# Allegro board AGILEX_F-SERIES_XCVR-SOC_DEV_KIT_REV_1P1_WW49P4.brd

Outline 218.44 x 218.44 mm; copper layers: TOP, GND02, ART03, GND04, ART05, GND06, ART07, GND08, POWER09, GND10, POWER11, POWER12, GND13, POWER14, GND15, ART16, GND17, ART18, GND19, ART20, GND21, BOTTOM. Coordinates in mm from the lower left corner of the outline.
Outline path: 0,217.17 arc(0.37,218.07) 1.27,218.44 217.17,218.44 arc(218.07,218.07) 218.44,217.17 218.44,1.27 arc(218.07,0.37) 217.17,0 1.27,0 arc(0.37,0.37) 0,1.27 0,217.17

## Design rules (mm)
constraint set DEFAULT: min track width 0.109
net group AGND_1.8V: nets EN_1.8V N25097889
net group AGND_2.5V: nets EN_2.5V N25103528
net group AGND_VCCIO_FPGA_1.2V: nets EN_VCCIO_FPGA_1.2V N25225151
net group AGND_VCCIO_FPGA_1.5V: nets EN_VCCIO_FPGA_1.5V N25087496
net group AGND_VCCIO_FPGA_1.8V: nets EN_VCCIO_FPGA_1.8V N25083983
net group AGND_VCCL_HPS_FPGA_0.9V: nets EN_VCCL_HPS_FPGA_0.9V N25074810
net group AGND_VCCL_SDM_FPGA_0.8V: nets EN_VCCL_SDM_FPGA_0.8V N25076947
net group AVST_CLK: nets AVST_CLK N18693741
net group CLEANER_IN0_N: nets CLEANER_IN0_N CLEARNER_RECOVERY_N0
net group CLEANER_IN0_P: nets CLEANER_IN0_P CLEARNER_RECOVERY_P0
net group CLEANER_IN1_N: nets CLEANER_IN1_N CLEARNER_RECOVERY_N1
net group CLEANER_IN1_P: nets CLEANER_IN1_P CLEARNER_RECOVERY_P1
net group CLEANER_IN2_N: nets CLEANER_IN2_N CLEARNER_RECOVERY_N2
net group CLEANER_IN2_P: nets CLEANER_IN2_P CLEARNER_RECOVERY_P2
net group CLK_50M_PWRMAX: nets CLK_50M_PWRMAX N17552752
net group CLK_50M_SYSMAX: nets CLK_50M_SYSMAX N18161617
net group CLS_40OHM: nets DDR4_COMP_ALERTN DDR4_COMP_RESETN
net group CLS_EXT_JTAG: nets JTAG_RX JTAG_TX
net group CLS_FX2: nets FX2_RESETN FX2_WAKEUP
net group CLS_FX2_USB: nets FX2_DN FX2_DP
net group CLS_GND_E: nets GND_ETHE GND_QSFP_CAGE
net group CLS_MEMORY_DDR4_CAC: nets DDR4_COMP_RZQ DDR4_COMP_TEN
net group CLS_SODIMM_CLK: nets MEM_CLKN MEM_CLKP
net group CLS_SODIMM_D8: nets MEM_DQ_ADDR_CMD4 MEM_DQ_ADDR_CMD7
net group DIFFPAIR19: nets N17498635 N17498650
net group DIFFPAIR20: nets N17498657 N17498668
net group DIFFPAIR21: nets N17498677 N17498690
net group DIFFPAIR22: nets N17498697 N17498704
net group DIFFPAIR23: nets N18253290 N18253428
net group DIFFPAIR24: nets N18253296 N18253441
net group DIFFPAIR25: nets N18253303 N18253449
net group DIFFPAIR26: nets N18253309 N18253452
net group EN0_1.8V_R: nets EN0_1.8V_R EN_VCCPT_FPGA_1.8V
net group EN0_3.3V_R: nets EN0_3.3V_R EN_3.3V
net group EN_1.2V: nets EN_1.2V N25917150
net group EN_VCCCLK_GXE_FPGA_2.5V: nets EN_VCCCLK_GXE_FPGA_2.5V N25909453
net group EN_VCCFUSEWR_SDM_FPGA_2.4V: nets EN_VCCFUSEWR_SDM_FPGA_2.4V N25913473
net group EN_VCCH_GXE_FPGA_1.1V: nets EN_VCCH_GXE_FPGA_1.1V N25080456
net group EN_VTT_DDR4_0.6V: nets EN_VTT_DDR4_0.6V N24985018
net group EN_VTT_SODIMM_0.6V: nets EN_VTT_SODIMM_0.6V N24984146
net group ETH_T_SGMII_TXN: nets ETH_SGMII_TXN ETH_T_SGMII_TXN
net group ETH_T_SGMII_TXP: nets ETH_SGMII_TXP ETH_T_SGMII_TXP
net group FAN_RPM: nets FAN_RPM N18990186
net group FLASH_DC0_IO0: nets FLASH_DC0_IO0 SDM_IO2
net group FLASH_DC0_IO2: nets FLASH_DC0_IO2 SDM_IO5
net group FLASH_DC0_IO3: nets FLASH_DC0_IO3 SDM_IO1
net group FLASH_DC0_IO5: nets FLASH_DC0_IO5 SDM_IO6
net group FLASH_DC0_IO6: nets FLASH_DC0_IO6 SDM_IO9
net group FLASH_DC0_IO7: nets FLASH_DC0_IO7 SDM_IO7
net group FLASH_DC0_IO9: nets FLASH_DC0_IO9 SDM_IO13
net group FLASH_DC0_IO12: nets SDM_IO11 SDM_IO16
net group FPGA_GPIO_OUTCLKN: nets FPGA_GPIO_OUTCLKN N18623017
net group FPGA_GPIO_OUTCLKP: nets FPGA_GPIO_OUTCLKP N18624759
net group FPGA_GPIO_REFCLK: nets FPGA_GPIO_REFCLK SI5338_1_CLK2P
net group FPGA_GPIO_REFCLKN2: nets FPGA_GPIO_REFCLKN2 N18624288
net group FPGA_GPIO_REFCLKP2: nets FPGA_GPIO_REFCLKP2 N18624358
net group FPGA_SYSTEM_CLK: nets FPGA_SYSTEM_CLK SI5338_1_CLK0P
net group FPGA_TEMP0: nets FPGA_TEMP0N FPGA_TEMP0P
net group FPGA_TEMP1: nets FPGA_TEMP1N FPGA_TEMP1P
net group FPGA_TEMP2: nets FPGA_TEMP2N FPGA_TEMP2P
net group FPGA_TEMP3: nets FPGA_TEMP3N FPGA_TEMP3P
net group FX2_SCL: nets FX2_SCL PHY_SCL
net group FX2_SDA: nets FX2_SDA PHY_SDA
net group GNDSENSE: nets GNDSENSE VCCLSENSE
net group HPS_GPIO28: nets HPS_GPIO28 HPS_GPIO28_R
net group HPS_GPIO29: nets HPS_GPIO29 HPS_GPIO29_R
net group I2C_3.3V_SDA: nets I2C_3.3V_SCL I2C_3.3V_SDA
net group I2C_PCIE_SCL: nets I2C_PCIE_SCL N20316912
net group I2C_PCIE_SDA: nets I2C_PCIE_SDA N20316908
net group I2C_VID_SDA: nets I2C_VID_SCL I2C_VID_SDA
net group ISENSE_12VIN: nets ISENSE_12VIN N18163063
net group ISENSEN_VCCIO_FPGA_1.8V: nets ISENSEN_VCCIO_FPGA_1.8V ISENSEP_VCCIO_FPGA_1.8V
net group ISENSEP_VCCCLK_GXE_FPGA_2.5V: nets ISENSEN_VCCCLK_GXE_FPGA_2.5V ISENSEP_VCCCLK_GXE_FPGA_2.5V
net group ISENSEP_VCCFUSEWR_SDM_FPGA_2.4V: nets ISENSEN_VCCFUSEWR_SDM_FPGA_2.4V ISENSEP_VCCFUSEWR_SDM_FPGA_2.4V
net group ISENSEP_VCCH_GXE_FPGA_1.1V: nets ISENSEN_VCCH_GXE_FPGA_1.1V ISENSEP_VCCH_GXE_FPGA_1.1V
net group ISENSEP_VCCIO_FPGA_1.5V: nets ISENSEN_VCCIO_FPGA_1.5V ISENSEP_VCCIO_FPGA_1.5V
net group ISENSEP_VCCL_HPS_FPGA_0.9V: nets ISENSEN_VCCL_HPS_FPGA_0.9V ISENSEP_VCCL_HPS_FPGA_0.9V
net group ISENSEP_VCCL_SDM_FPGA_0.8V: nets ISENSEN_VCCL_SDM_FPGA_0.8V ISENSEP_VCCL_SDM_FPGA_0.8V
net group ISENSEP_VDD_SODIMM: nets ISENSEN_VDD_SODIMM ISENSEP_VDD_SODIMM
net group MG_AVST_U29-U1: nets AVST_D24 AVST_READY
net group MXP_RXP0: nets MXP_RXN0 MXP_RXP0
net group MXP_RXP1: nets MXP_RXN1 MXP_RXP1
net group MXP_RXP2: nets MXP_RXN2 MXP_RXP2
net group MXP_RXP3: nets MXP_RXN3 MXP_RXP3
net group MXP_TXP0: nets MXP_TXN0 MXP_TXP0
net group MXP_TXP1: nets MXP_TXN1 MXP_TXP1
net group MXP_TXP2: nets MXP_TXN2 MXP_TXP2
net group MXP_TXP3: nets MXP_TXN3 MXP_TXP3
net group N18609511: nets N18609511 N19994522
net group N19994036: nets N19994036 N21454939
net group N20035742: nets N20035658 N20035742
net group OPT_FAN_RPM: nets N18990913 OPT_FAN_RPM
net group PCIE_RC_REFCLKN: nets N20604746 PCIE_RC_REFCLKN
net group PCIE_RC_REFCLKP: nets N20604729 PCIE_RC_REFCLKP
net group PCIE_RC_RXP0: nets PCIE_RC_RXN0 PCIE_RC_RXP0
net group PCIE_RC_RXP1: nets PCIE_RC_RXN1 PCIE_RC_RXP1
net group PCIE_RC_RXP2: nets PCIE_RC_RXN2 PCIE_RC_RXP2
net group PCIE_RC_RXP3: nets PCIE_RC_RXN3 PCIE_RC_RXP3
net group PCIE_RC_RXP4: nets PCIE_RC_RXN4 PCIE_RC_RXP4
net group PCIE_RC_RXP5: nets PCIE_RC_RXN5 PCIE_RC_RXP5
net group PCIE_RC_RXP6: nets PCIE_RC_RXN6 PCIE_RC_RXP6
net group PCIE_RC_RXP7: nets PCIE_RC_RXN7 PCIE_RC_RXP7
net group PCIE_RC_RXP8: nets PCIE_RC_RXN8 PCIE_RC_RXP8
net group PCIE_RC_RXP9: nets PCIE_RC_RXN9 PCIE_RC_RXP9
net group PCIE_RC_RXP10: nets PCIE_RC_RXN10 PCIE_RC_RXP10
net group PCIE_RC_RXP11: nets PCIE_RC_RXN11 PCIE_RC_RXP11
net group PCIE_RC_RXP12: nets PCIE_RC_RXN12 PCIE_RC_RXP12
net group PCIE_RC_RXP13: nets PCIE_RC_RXN13 PCIE_RC_RXP13
net group PCIE_RC_RXP14: nets PCIE_RC_RXN14 PCIE_RC_RXP14
net group PCIE_RC_RXP15: nets PCIE_RC_RXN15 PCIE_RC_RXP15
net group PCIE_RC_TXP0: nets PCIE_RC_TXN0 PCIE_RC_TXP0
net group PCIE_RC_TXP1: nets PCIE_RC_TXN1 PCIE_RC_TXP1
net group PCIE_RC_TXP2: nets PCIE_RC_TXN2 PCIE_RC_TXP2
net group PCIE_RC_TXP3: nets PCIE_RC_TXN3 PCIE_RC_TXP3
net group PCIE_RC_TXP4: nets PCIE_RC_TXN4 PCIE_RC_TXP4
net group PCIE_RC_TXP5: nets PCIE_RC_TXN5 PCIE_RC_TXP5
net group PCIE_RC_TXP6: nets PCIE_RC_TXN6 PCIE_RC_TXP6
net group PCIE_RC_TXP7: nets PCIE_RC_TXN7 PCIE_RC_TXP7
net group PCIE_RC_TXP8: nets PCIE_RC_TXN8 PCIE_RC_TXP8
net group PCIE_RC_TXP9: nets PCIE_RC_TXN9 PCIE_RC_TXP9
net group PCIE_RC_TXP10: nets PCIE_RC_TXN10 PCIE_RC_TXP10
net group PCIE_RC_TXP11: nets PCIE_RC_TXN11 PCIE_RC_TXP11
net group PCIE_RC_TXP12: nets PCIE_RC_TXN12 PCIE_RC_TXP12
net group PCIE_RC_TXP13: nets PCIE_RC_TXN13 PCIE_RC_TXP13
net group PCIE_RC_TXP14: nets PCIE_RC_TXN14 PCIE_RC_TXP14
net group PCIE_RC_TXP15: nets PCIE_RC_TXN15 PCIE_RC_TXP15
net group PCIE_TXN0: nets PCIE_TXN0 PCIE_TXP0
net group PCIE_TXN3: nets PCIE_TXN3 PCIE_TXP3
net group PCIE_TXP1: nets PCIE_TXN1 PCIE_TXP1
net group PCIE_TXP2: nets PCIE_TXN2 PCIE_TXP2
net group PCIE_TXP4: nets PCIE_TXN4 PCIE_TXP4
net group PCIE_TXP5: nets PCIE_TXN5 PCIE_TXP5
net group PCIE_TXP6: nets PCIE_TXN6 PCIE_TXP6
net group PCIE_TXP7: nets PCIE_TXN7 PCIE_TXP7
net group PCIE_TXP8: nets PCIE_TXN8 PCIE_TXP8
net group PCIE_TXP9: nets PCIE_TXN9 PCIE_TXP9
net group PCIE_TXP10: nets PCIE_TXN10 PCIE_TXP10
net group PCIE_TXP11: nets PCIE_TXN11 PCIE_TXP11
net group PCIE_TXP12: nets PCIE_TXN12 PCIE_TXP12
net group PCIE_TXP13: nets PCIE_TXN13 PCIE_TXP13
net group PCIE_TXP14: nets PCIE_TXN14 PCIE_TXP14
net group PCIE_TXP15: nets PCIE_TXN15 PCIE_TXP15
net group PWRMAX_DEBUGMDN: nets N20307193 PWRMAX_DEBUGMDN
net group QSFPDD_RXP0: nets QSFPDD_RXN0 QSFPDD_RXP0
net group QSFPDD_RXP1: nets QSFPDD_RXN1 QSFPDD_RXP1
net group QSFPDD_RXP2: nets QSFPDD_RXN2 QSFPDD_RXP2
net group QSFPDD_RXP3: nets QSFPDD_RXN3 QSFPDD_RXP3
net group QSFPDD_RXP4: nets QSFPDD_RXN4 QSFPDD_RXP4
net group QSFPDD_RXP5: nets QSFPDD_RXN5 QSFPDD_RXP5
net group QSFPDD_RXP6: nets QSFPDD_RXN6 QSFPDD_RXP6
net group QSFPDD_RXP7: nets QSFPDD_RXN7 QSFPDD_RXP7
net group QSFPDD_TEMP4P: nets QSFPDD_TEMP4N QSFPDD_TEMP4P
net group QSFPDD_TXP0: nets QSFPDD_TXN0 QSFPDD_TXP0
net group QSFPDD_TXP1: nets QSFPDD_TXN1 QSFPDD_TXP1
net group QSFPDD_TXP2: nets QSFPDD_TXN2 QSFPDD_TXP2
net group QSFPDD_TXP3: nets QSFPDD_TXN3 QSFPDD_TXP3
net group QSFPDD_TXP4: nets QSFPDD_TXN4 QSFPDD_TXP4
net group QSFPDD_TXP5: nets QSFPDD_TXN5 QSFPDD_TXP5
net group QSFPDD_TXP6: nets QSFPDD_TXN6 QSFPDD_TXP6
net group QSFPDD_TXP7: nets QSFPDD_TXN7 QSFPDD_TXP7
net group REFCLK_GXEN1: nets N18946522 REFCLK_GXEN1
net group REFCLK_GXEP1: nets N18946492 REFCLK_GXEP1
net group REFCLK_GXPN0: nets N20604632 REFCLK_GXPN0
net group REFCLK_GXPN2: nets N20604666 REFCLK_GXPN2
net group REFCLK_GXPP0: nets N20604615 REFCLK_GXPP0
net group REFCLK_GXPP2: nets N20604649 REFCLK_GXPP2
net group REFERENCECLK_2: nets CLEARNER_7_1HZ REFERENCECLK_2
net group REFERENCECLK_3: nets CLEARNER_0_1HZ REFERENCECLK_3
net group SMA_REFCLKN: nets N17579380 SMA_REFCLKN
net group SMA_REFCLKP: nets N17579378 SMA_REFCLKP
net group SODIMM_CMD4-5: nets MEM_ADDR_CMD4 MEM_ADDR_CMD5
net group SODIMM_VDDQ_AGND: nets EN_VDD_SODIMM N25093122
net group VCCBAT: nets VCCBAT VCCBAT_FPGA_1.8V
net group VSENSEP_VCC/VSENSEN_VCC: nets VSENSEN_VCC VSENSEP_VCC
net group VSENSEP_VCCH: nets VSENSEN_VCCH VSENSEP_VCCH
net group ZQSFP_RXP0: nets ZQSFP_RXN0 ZQSFP_RXP0
net group ZQSFP_RXP1: nets ZQSFP_RXN1 ZQSFP_RXP1
net group ZQSFP_RXP2: nets ZQSFP_RXN2 ZQSFP_RXP2
net group ZQSFP_RXP3: nets ZQSFP_RXN3 ZQSFP_RXP3
net group ZQSFP_TXP0: nets ZQSFP_TXN0 ZQSFP_TXP0
net group ZQSFP_TXP1: nets ZQSFP_TXN1 ZQSFP_TXP1
net group ZQSFP_TXP2: nets ZQSFP_TXN2 ZQSFP_TXP2
net group ZQSFP_TXP3: nets ZQSFP_TXN3 ZQSFP_TXP3
net group CLEARNER_SYSTEM_N: nets CLEARNER_SYSTEM_N N20550319 N20550321
net group CLEARNER_SYSTEM_P: nets CLEARNER_SYSTEM_P N20550259 N20550288
net group CLK_SE: nets FPGA_OSC_CLK_1
net group CLS_45OHM: nets MEM_ADDR_CMD0 MEM_ADDR_CMD1 MEM_ADDR_CMD2 MEM_ADDR_CMD3 MEM_ADDR_CMD8 MEM_ADDR_CMD9 MEM_ADDR_CMD10 MEM_ADDR_CMD11 MEM_ADDR_CMD12 MEM_ADDR_CMD13 MEM_ADDR_CMD14 MEM_ADDR_CMD15 MEM_ADDR_CMD16 MEM_ADDR_CMD17 MEM_ADDR_CMD18 MEM_ADDR_CMD19 MEM_ADDR_CMD20 MEM_ADDR_CMD21 MEM_ADDR_CMD22 MEM_ADDR_CMD23 MEM_ADDR_CMD24 MEM_ADDR_CMD25 MEM_ADDR_CMD26 MEM_ADDR_CMD28 MEM_ADDR_CMD29 MEM_ADDR_CMD30
net group CLS_CLEANER: nets CLEANER_HW_CTRL CLEANER_STATUS0 CLEANER_STATUS1
net group CLS_CLK_DIFF: nets SI5338_0_CLK0P
net group CLS_CLKCLEANER: nets CLKCLEANER_IO_TSN CLKCLEANER_STATUS0 CLKCLEANER_STATUS1
net group CLS_FLASH_DC0: nets FLASH_DC0_PRSNTN
net group CLS_FLASH_DC1_IO: nets FLASH_DC1_PRSNTN
net group CLS_FPGA_DNU: nets FPGA_DNU_CORE0 FPGA_DNU_CORE1 FPGA_DNU_CORE2 FPGA_DNU_CORNER0 FPGA_DNU_CORNER1 FPGA_DNU_CORNER2 FPGA_DNU_CORNER3 FPGA_DNU_CORNER4 FPGA_DNU_CORNER5 FPGA_DNU_CORNER6 FPGA_DNU_CORNER7 FPGA_DNU_SDM0 FPGA_DNU_SDM1
net group CLS_FPGA_GPIO: nets FPGA_GPIO0 FPGA_GPIO1 FPGA_GPIO2 FPGA_GPIO3 FPGA_GPIO4 FPGA_GPIO5 FPGA_GPIO6 FPGA_GPIO7 FPGA_GPIO8 FPGA_GPIO9 FPGA_GPIO10 FPGA_GPIO11 FPGA_GPIO12 FPGA_GPIO13 FPGA_GPIO14 FPGA_GPIO15
net group CLS_FPGA_PB: nets FPGA_PB0 FPGA_PB1 FPGA_PB2 FPGA_PB3 FPGA_PB4 FPGA_PB5 FPGA_PB6 FPGA_PB7 FPGA_SW0 FPGA_SW1 FPGA_SW2 FPGA_SW3 FPGA_SW4 FPGA_SW5 FPGA_SW6 FPGA_SW7
net group CLS_HPS: nets HPS_DC_PRSNTN HPS_DC_RESETN HPS_PWREN HPS_PWRGD
net group CLS_I2C: nets CLEANER_SCL CLEANER_SDA CLKCLEANER_SCL CLKCLEANER_SDA F2M_I2C_SCL F2M_I2C_SDA FPGA_TEST_SCL FPGA_TEST_SDA FPGA_TESTI2C_SCL FPGA_TESTI2C_SDA M2F_I2C_SCL M2F_I2C_SDA MAX_SCL MAX_SDA QSFP_I2C_SCL QSFP_I2C_SDA QSFPDD_I2C_SCL QSFPDD_I2C_SDA QSFPDD_T_SCL QSFPDD_T_SDA SDM_I2C_SCL SDM_I2C_SDA SODIMM_I2C_SCL SODIMM_I2C_SDA SODIMM_SCL SODIMM_SDA ZQSFP_T_SCL ZQSFP_T_SDA
net group CLS_ISENSEN: nets VSENSE_3.3V_PRE VSENSE_5V VSENSE_12VIN
net group CLS_LED: nets ETH_LED_LINK10 ETH_LED_LINK100 ETH_LED_LINK1000 ETH_LED_RX ETH_LED_TX FPGA_LED_G0 FPGA_LED_G1 FPGA_LED_G2 FPGA_LED_G3 FPGA_LED_G4 FPGA_LED_G5 FPGA_LED_G6 FPGA_LED_G7 PWRMAX_LED_G0 PWRMAX_LED_G1 PWRMAX_LED_R0 PWRMAX_LED_R1 SYSMAX_LED_G0 SYSMAX_LED_G1 SYSMAX_LED_G2 SYSMAX_LED_G3 SYSMAX_LED_G4 SYSMAX_LED_Y0 SYSMAX_LED_Y1
net group CLS_MEMORY_DDR4_0: nets DDR4_COMP_DBIN0 DDR4_COMP_DQ0 DDR4_COMP_DQ2 DDR4_COMP_DQ4 DDR4_COMP_DQ6
net group CLS_MEMORY_DDR4_1: nets DDR4_COMP_DBIN1 DDR4_COMP_DQ8 DDR4_COMP_DQ9 DDR4_COMP_DQ10 DDR4_COMP_DQ11 DDR4_COMP_DQ12 DDR4_COMP_DQ13 DDR4_COMP_DQ14 DDR4_COMP_DQ15
net group CLS_MEMORY_DDR4_2: nets DDR4_COMP_DBIN2 DDR4_COMP_DQ16 DDR4_COMP_DQ17 DDR4_COMP_DQ18 DDR4_COMP_DQ19 DDR4_COMP_DQ20 DDR4_COMP_DQ21 DDR4_COMP_DQ22 DDR4_COMP_DQ23
net group CLS_MEMORY_DDR4_3: nets DDR4_COMP_DBIN3 DDR4_COMP_DQ24 DDR4_COMP_DQ25 DDR4_COMP_DQ26 DDR4_COMP_DQ27 DDR4_COMP_DQ28 DDR4_COMP_DQ29 DDR4_COMP_DQ30 DDR4_COMP_DQ31
net group CLS_MEMORY_DDR4_4: nets DDR4_COMP_DBIN4 DDR4_COMP_DQ32 DDR4_COMP_DQ33 DDR4_COMP_DQ34 DDR4_COMP_DQ35 DDR4_COMP_DQ36 DDR4_COMP_DQ37 DDR4_COMP_DQ38 DDR4_COMP_DQ39
net group CLS_MEMORY_DDR4_5: nets DDR4_COMP_DBIN5 DDR4_COMP_DQ40 DDR4_COMP_DQ41 DDR4_COMP_DQ42 DDR4_COMP_DQ43 DDR4_COMP_DQ44 DDR4_COMP_DQ45 DDR4_COMP_DQ46 DDR4_COMP_DQ47
net group CLS_MEMORY_DDR4_6: nets DDR4_COMP_DBIN6 DDR4_COMP_DQ48 DDR4_COMP_DQ49 DDR4_COMP_DQ50 DDR4_COMP_DQ51 DDR4_COMP_DQ52 DDR4_COMP_DQ53 DDR4_COMP_DQ54 DDR4_COMP_DQ55
net group CLS_MEMORY_DDR4_7: nets DDR4_COMP_DBIN7 DDR4_COMP_DQ56 DDR4_COMP_DQ57 DDR4_COMP_DQ58 DDR4_COMP_DQ59 DDR4_COMP_DQ60 DDR4_COMP_DQ61 DDR4_COMP_DQ62 DDR4_COMP_DQ63
net group CLS_MEMORY_DDR4_8: nets DDR4_COMP_DBIN8 DDR4_COMP_DQ64 DDR4_COMP_DQ65 DDR4_COMP_DQ66 DDR4_COMP_DQ68 DDR4_COMP_DQ70 DDR4_COMP_DQ71
net group CLS_MEMORY_DDR4_DQS: nets DDR4_COMP_DQSN0 DDR4_COMP_DQSN1 DDR4_COMP_DQSN2 DDR4_COMP_DQSN3 DDR4_COMP_DQSN4 DDR4_COMP_DQSN5 DDR4_COMP_DQSN6 DDR4_COMP_DQSN7 DDR4_COMP_DQSP0 DDR4_COMP_DQSP1 DDR4_COMP_DQSP2 DDR4_COMP_DQSP3 DDR4_COMP_DQSP4 DDR4_COMP_DQSP5 DDR4_COMP_DQSP6 DDR4_COMP_DQSP7 DDR4_COMP_DQSP8
net group CLS_POWER_20MIL: nets 2.5V_PRE
net group CLS_RST: nets ETH_RSTN ETH_T_RSTN EXT_PROC_RSTN FLASH_DC0_RSTN FLASH_DC1_RSTN FPGA_NSTATUS FPGA_SYS_RESETN FPGA_TEST_ALERTN FPGA_TESTI2C_ALERTN FPGA_TESTI2C_TSN HPS_PROC_RSTN PCIE_EP_PERSTN PCIE_RC_JTAG_TRSTN PCIE_RC_PERSTN PCIE_RC_PRSNTN PWRMAX_PORSTN
net group CLS_SODIMM_D1: nets MEM_DMAN1 MEM_DQA8 MEM_DQA9 MEM_DQA10 MEM_DQA11 MEM_DQA12 MEM_DQA13 MEM_DQA14 MEM_DQA15
net group CLS_SODIMM_D2: nets MEM_DMAN2
net group CLS_SODIMM_D3: nets MEM_DMAN3 MEM_DQA24 MEM_DQA25 MEM_DQA26 MEM_DQA27 MEM_DQA28 MEM_DQA29 MEM_DQA30 MEM_DQA31
net group CLS_SODIMM_D4: nets MEM_DMBN0 MEM_DQB0 MEM_DQB1 MEM_DQB2 MEM_DQB3 MEM_DQB4 MEM_DQB5 MEM_DQB6 MEM_DQB7
net group CLS_SODIMM_D5: nets MEM_DMBN1 MEM_DQB8 MEM_DQB9 MEM_DQB10 MEM_DQB11 MEM_DQB12 MEM_DQB13 MEM_DQB14 MEM_DQB15
net group CLS_SODIMM_D6: nets MEM_DMBN2 MEM_DQB16 MEM_DQB17 MEM_DQB18 MEM_DQB19 MEM_DQB20 MEM_DQB21 MEM_DQB22 MEM_DQB23
net group CLS_SODIMM_D7: nets MEM_DMBN3 MEM_DQB24 MEM_DQB25 MEM_DQB26 MEM_DQB27 MEM_DQB28 MEM_DQB29 MEM_DQB30 MEM_DQB31 MEM_DQB33
net group CLS_SODIMM_DQS: nets MEM_DQS_ADDR_CMDN MEM_DQS_ADDR_CMDP MEM_DQSAN1 MEM_DQSAN2 MEM_DQSAN3 MEM_DQSAP1 MEM_DQSAP2 MEM_DQSAP3 MEM_DQSBN0 MEM_DQSBN1 MEM_DQSBN2 MEM_DQSBN3 MEM_DQSBP0 MEM_DQSBP1 MEM_DQSBP2 MEM_DQSBP3
net group CLS_SYSMAX_JTAG: nets SYSMAX_JTAG_BYPASSN
net group CLS_XTAL: nets 24M_XTALIN 24M_XTALOUT ETH_XTAL_25MHZ
net group DDR4_COMP_64-71: nets DDR4_COMP_DQSN8
net group DDR4_COMP_REFCLKN: nets DDR4_COMP_REFCLKN N18606472 SI5338_1_CLK1N
net group DDR4_COMP_REFCLKP: nets DDR4_COMP_REFCLKP N18161939 SI5338_1_CLK1P
net group EN_12V: nets EN_12V N396890 N25560953
net group FLASH_DC0_IO1: nets SDM_IO4
net group FLASH_DC0_IO4: nets SDM_IO3
net group FLASH_DC0_IO8: nets SDM_IO8
net group FLASH_DC0_IO10: nets SDM_IO15
net group FLASH_DC0_IO11: nets SDM_IO10
net group FLASH_DC0_IO13: nets SDM_IO14
net group FLASH_DC0_IO14: nets SDM_IO12
net group FPGA_GPIO_REFCLKN0: nets FPGA_GPIO_REFCLKN0 N17585200 N18602360
net group FPGA_GPIO_REFCLKN1: nets FPGA_GPIO_REFCLKN1 N18602409 SI5338_0_CLK2N
net group FPGA_GPIO_REFCLKP0: nets FPGA_GPIO_REFCLKP0 N17585199 N18602357
net group FPGA_GPIO_REFCLKP1: nets FPGA_GPIO_REFCLKP1 N18602412 SI5338_0_CLK2P
net group FX2_PD2: nets FX2_PD2
net group FX2_PD3: nets FX2_PD3
net group HPS_DC_JTAG_TCK: nets HPS_DC_JTAG_TCK
net group HPS_GPIO31: nets N18056724
net group I2C_ALERTN_R: nets ADI_I2C_SCL I2C_ADI_SCL I2C_ALERTN_R LTM4678_1_VDD33
net group I2C_ALERTN_R_1: nets ADI_I2C_SDA I2C_ADI_SDA I2C_ALERTN_R_1 LTM4678_2_VDD33
net group MG_FLASH_DC_ALL(U29-J10-J11): nets FLASH_DC1_IO0 FLASH_DC1_IO1 FLASH_DC1_IO2 FLASH_DC1_IO3 FLASH_DC1_IO4 FLASH_DC1_IO5 FLASH_DC1_IO6 FLASH_DC1_IO7 FLASH_DC1_IO8 FLASH_DC1_IO9 FLASH_DC1_IO10 FLASH_DC1_IO11 FLASH_DC1_IO12 FLASH_DC1_IO13 FLASH_DC1_IO14 FLASH_DC1_IO15 FLASH_DC1_IO16 FLASH_DC1_IO17 FLASH_DC1_IO18 FLASH_DC1_IO19 FLASH_DC1_IO20 FLASH_DC1_IO21 FLASH_DC1_IO22 FLASH_DC1_IO23 FLASH_DC1_IO24 FLASH_DC1_IO25 FLASH_DC1_IO26 FLASH_DC1_IO27 FLASH_DC1_IO28 FLASH_DC1_IO29 FLASH_DC1_IO30 FLASH_DC1_IO31 FLASH_DC1_IO32 FLASH_DC1_IO33 FLASH_DC1_IO34 FLASH_DC1_IO35 FLASH_DC1_IO36 FLASH_DC1_IO37 FLASH_DC1_IO38 FLASH_DC1_IO39
net group MG_FX2_U21-U23: nets FX2_FLAGA FX2_FLAGB FX2_FLAGC FX2_SLRDN FX2_SLWRN
net group N24081: nets N24075 N24081 N20035759
net group N17771286: nets N17771286 N17771287 N18403594 N18524153 N20439947
net group N17771288: nets N17771288 N17771289 N18403603 N18524156 N20439969
net group NG_FPGA_TESTIO: nets FPGA_TESTIO0
net group REFCLK_GXEN0: nets N18127388 N18402344 REFCLK_GXEN0
net group REFCLK_GXEN2: nets N17395836 N18946341 REFCLK_GXEN2
net group REFCLK_GXEN3: nets N17771292 N18946378 REFCLK_GXEN3
net group REFCLK_GXEP0: nets N17579486 N18402365 REFCLK_GXEP0
net group REFCLK_GXEP2: nets N18946338 N19604697 REFCLK_GXEP2
net group REFCLK_GXEP3: nets N17771290 N18946381 REFCLK_GXEP3
net group REFERENCECLK_1: nets N18669847 N19548147 REFERENCECLK_1
net group SI549_CLKN: nets N17579627 N18947380 SI549_CLKN
net group SI549_CLKP: nets N17579701 N18947324 SI549_CLKP
net group SI53311_CLKOUT1N: nets N17585196 N18127220 SI53311_CLKOUT1N
net group SI53311_CLKOUT1P: nets N17585195 N18127283 SI53311_CLKOUT1P
net group SI53311_CLKSEL: nets N18126676 N20209521 SI53311_CLKSEL
net group SODIMM_DQS1: nets MEM_DQA32
net group SODIMM_DQS3: nets MEM_DQA33
net group SODIMM_DQS4: nets MEM_DQB32
net group SODIMM_DQS8: nets MEM_DQ_ADDR_CMD0 MEM_DQ_ADDR_CMD1 MEM_DQ_ADDR_CMD2 MEM_DQ_ADDR_CMD3 MEM_DQ_ADDR_CMD5 MEM_DQ_ADDR_CMD6 MEM_DQ_ADDR_CMD8
net group SODIMM_REFCLKN: nets N18606410 SI5338_0_CLK1N SODIMM_REFCLKN
net group SODIMM_REFCLKP: nets N18161324 SI5338_0_CLK1P SODIMM_REFCLKP
net group USB_FPGA_CLK: nets USB_FPGA_CLK
net group USB_T_CLK: nets USB_T_CLK

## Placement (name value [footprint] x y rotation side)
B1  Molex_zQSFP_Cage  [MOLEX_ZQSFP_CAGE]  29.02 103.24 90 top
BT1  Battery  [BT1]  118.55 38.2 0 bottom
C1  1uF  [0402]  156.7 76.2 90 top
C2  0.1uF  [0402]  54.36 147.55 180 top
C3  0.1uF  [0402]  55.6 147.52 180 top
C4  10uF  [0603]  56.49 158.39 90 top
C5  0.1uF  [0402]  53.95 158.04 0 top
C6  10uF  [0603]  32.05 156.01 270 top
C7  0.1uF  [0402]  38.1 146.63 180 top
C8  12pF  [0402]  38.35 158.62 0 top
C9  0.1uF  [0201]  63.75 37.08 270 top
C10  0.1uF  [0201]  62.74 37.08 270 top
C11  0.1uF  [0402]  106.55 101.83 120 bottom
C12  22uF  [0805]  67.28 106.04 90 bottom
C13  DNI  [1206]  67.28 103.5 180 bottom
C14  1uF  [0201]  109.16 110.85 150 bottom
C15  1uF  [0201]  106.13 112.1 90 bottom
C16  10uF  [0603]  100.18 125.22 270 bottom
C17  10uF  [0402]  103.97 108.85 240 bottom
C18  4.7uF  [0402]  111.76 109.85 300 bottom
C19  4.7uF  [0402]  119.55 96.35 120 bottom
C20  4.7uF  [0402]  108.3 109.85 300 bottom
C21  4.7uF  [0402]  107.43 93.35 120 bottom
C22  4.7uF  [0402]  119.55 95.35 120 bottom
C23  4.7uF  [0402]  104.83 98.85 300 bottom
C24  4.7uF  [0402]  113.49 109.85 300 bottom
C25  4.7uF  [0402]  119.55 108.35 120 bottom
C26  4.7uF  [0402]  112.63 93.35 120 bottom
C27  4.7uF  [0402]  110.89 107.35 120 bottom
C28  4.7uF  [0402]  114.36 93.35 120 bottom
C29  4.7uF  [0402]  109.16 93.35 120 bottom
C30  4.7uF  [0402]  110.89 93.35 120 bottom
C31  4.7uF  [0402]  104.83 104.85 300 bottom
C32  4.7uF  [0402]  115.22 95.85 300 bottom
C33  4.7uF  [0402]  104.83 102.85 300 bottom
C34  4.7uF  [0402]  110.03 108.85 300 bottom
C35  4.7uF  [0402]  104.83 100.85 300 bottom
C36  4.7uF  [0402]  114.36 107.35 120 bottom
C37  4.7uF  [0402]  104.83 106.85 300 bottom
C38  10uF  [0402]  103.97 107.85 240 bottom
C39  1uF  [0201]  123.02 91.85 150 bottom
C40  1uF  [0201]  123.02 92.85 150 bottom
C41  4.7uF  [0402]  103.1 95.85 300 bottom
C42  4.7uF  [0402]  106.56 95.85 300 bottom
C43  4.7uF  [0402]  108.3 95.85 300 bottom
C44  4.7uF  [0402]  109.16 94.35 120 bottom
C45  4.7uF  [0402]  104.83 96.85 300 bottom
C46  4.7uF  [0402]  102.23 93.35 120 bottom
C47  4.7uF  [0402]  103.1 98.85 300 bottom
C48  4.7uF  [0402]  103.97 93.35 120 bottom
C49  4.7uF  [0402]  116.96 95.85 300 bottom
C50  4.7uF  [0402]  117.82 95.35 120 bottom
C71  1uF  [0201]  119.56 93.35 210 bottom
C73  1uF  [0201]  120.42 94.35 330 bottom
C74  1uF  [0201]  117.82 93.35 210 bottom
C75  1uF  [0201]  118.69 94.35 330 bottom
C76  10uF  [0603]  124.05 76.07 90 bottom
C77  10uF  [0603]  127.61 76.07 90 bottom
C78  1uF  [0201]  104.83 111.35 330 bottom
C79  1uF  [0201]  103.97 110.35 210 bottom
C80  47uF  [0805]  107.44 97.79 270 bottom
C81  47uF  [0805]  107.44 99.69 270 bottom
C82  47uF  [0805]  107.44 103.5 270 bottom
C83  47uF  [0805]  116.2 99.69 90 bottom
C84  47uF  [0805]  116.2 103.5 90 bottom
C85  47uF  [0805]  107.44 105.41 270 bottom
C87  47uF  [0805]  116.2 105.41 90 bottom
C88  47uF  [0805]  116.2 101.6 90 bottom
C89  47uF  [0805]  77.22 120.52 270 bottom
C90  47uF  [0805]  116.59 125.6 0 bottom
C91  47uF  [0805]  77.22 113.67 270 bottom
C92  47uF  [0805]  142.85 122.55 270 bottom
C93  47uF  [0805]  77.22 115.95 270 bottom
C94  47uF  [0805]  142.85 124.84 270 bottom
C95  47uF  [0805]  142.85 117.98 270 bottom
C96  47uF  [0805]  118.87 125.6 0 bottom
C97  47uF  [0805]  77.22 118.24 270 bottom
C98  47uF  [0805]  116.2 97.79 90 bottom
C99  47uF  [0805]  142.85 120.27 270 bottom
C100  47uF  [0805]  155.45 119.25 270 bottom
C101  47uF  [0805]  77.22 122.81 270 bottom
C102  47uF  [0805]  155.45 123.83 90 top
C103  47uF  [0805]  155.45 123.83 270 bottom
C104  47uF  [0805]  155.45 121.54 90 top
C105  47uF  [0805]  77.22 125.09 270 bottom
C106  47uF  [0805]  155.45 119.25 90 top
C107  47uF  [0805]  151.25 123.82 90 bottom
C108  47uF  [0805]  155.45 121.54 270 bottom
C109  47uF  [0805]  151.33 119.25 90 bottom
C120  1uF  [0201]  101.37 99.85 210 bottom
C121  1uF  [0201]  100.5 100.35 210 bottom
C122  1uF  [0201]  100.5 98.35 210 bottom
C124  1uF  [0201]  101.8 101.6 90 bottom
C125  1uF  [0201]  100.5 97.35 210 bottom
C126  1uF  [0201]  100.5 95.35 210 bottom
C127  1uF  [0201]  122.15 101.85 210 bottom
C130  1uF  [0201]  101.37 104.35 150 bottom
C132  1uF  [0201]  100.5 101.35 210 bottom
C133  1uF  [0201]  101.37 96.85 210 bottom
C134  1uF  [0201]  101.37 103.35 150 bottom
C135  1uF  [0201]  100.5 102.35 210 bottom
C136  1uF  [0201]  101.8 95.6 90 bottom
C139  1uF  [0201]  101.8 98.6 90 bottom
C140  0.1uF  [0402]  99.47 91.98 180 bottom
C141  47uF  [0805]  131.42 125.6 0 bottom
C142  47uF  [0805]  123.8 125.6 0 bottom
C143  47uF  [0805]  133.96 125.6 0 bottom
C144  47uF  [0805]  121.26 125.6 0 bottom
C145  47uF  [0805]  128.88 125.6 0 bottom
C146  47uF  [0805]  126.34 125.6 0 bottom
C147  22uF  [0603]  113.67 98.27 90 bottom
C148  22uF  [0603]  110.41 104.95 270 bottom
C149  22uF  [0603]  112.06 104.95 270 bottom
C150  22uF  [0603]  113.67 104.95 270 bottom
C151  1uF  [0201]  121.29 98.35 210 bottom
C152  1uF  [0201]  122.15 105.35 150 bottom
C153  1uF  [0201]  121.29 103.35 210 bottom
C154  1uF  [0201]  121.29 102.35 210 bottom
C155  1uF  [0201]  122.15 104.35 150 bottom
C156  1uF  [0201]  100.5 94.35 210 bottom
C157  1uF  [0201]  122.15 95.35 150 bottom
C158  1uF  [0201]  121.29 94.85 150 bottom
C159  1uF  [0201]  123.02 101.35 30 bottom
C160  1uF  [0201]  123.02 102.85 330 bottom
C161  1uF  [0201]  97.9 99.35 150 bottom
C162  1uF  [0201]  97.9 100.35 150 bottom
C163  10uF  [0402]  106.56 109.85 120 bottom
C164  22uF  [0603]  110.41 98.27 90 bottom
C165  22uF  [0603]  112.06 98.27 90 bottom
C166  1uF  [0201]  97.04 95.35 210 bottom
C167  1uF  [0201]  96.17 95.85 210 bottom
C168  1uF  [0201]  96.17 99.85 210 bottom
C169  1uF  [0201]  96.17 100.85 210 bottom
C170  1uF  [0201]  97.9 101.85 30 bottom
C171  1uF  [0201]  97.9 97.35 330 bottom
C172  1uF  [0201]  97.9 103.85 30 bottom
C173  1uF  [0201]  97.9 96.35 330 bottom
C175  1uF  [0201]  96.17 101.85 210 bottom
C176  1uF  [0201]  96.17 98.85 211.3 bottom
C177  1uF  [0201]  96.17 96.85 210 bottom
C178  1uF  [0201]  96.17 102.85 210 bottom
C179  1uF  [0201]  96.17 97.85 210 bottom
C180  1uF  [0201]  97.9 102.85 30 bottom
C181  10uF  [0603]  80.99 101.89 0 bottom
C182  4.7uF  [0201]  127.35 101.86 30 bottom
C183  4.7uF  [0201]  125.62 106.35 150 bottom
C184  4.7uF  [0201]  127.35 106.85 30 bottom
C185  4.7uF  [0201]  125.62 105.35 150 bottom
C186  4.7uF  [0201]  127.35 104.85 30 bottom
C187  4.7uF  [0201]  127.35 100.85 30 bottom
C188  1uF  [0201]  125.62 100.85 210 bottom
C189  1uF  [0201]  127.35 105.85 30 bottom
C190  1uF  [0201]  127.35 102.85 30 bottom
C191  1uF  [0201]  127.35 103.85 30 bottom
C192  100uF  [0805]  81.78 82.49 90 bottom
C193  100uF  [0805]  81.78 80.16 90 bottom
C194  10uF  [0603]  80.11 112.83 270 bottom
C195  4.7uF  [0603]  81.86 112.81 90 bottom
C196  4.7uF  [0603]  83.57 112.83 90 bottom
C197  1uF  [0201]  121.29 99.35 210 bottom
C198  1uF  [0201]  121.29 100.35 210 bottom
C199  10uF  [0603]  125.83 76.07 90 bottom
C201  1uF  [0201]  123.02 100.35 30 bottom
C202  4.7uF  [0603]  75.28 95.38 0 bottom
C203  10uF  [0603]  149.96 108.61 90 bottom
C204  10uF  [0603]  148.31 108.61 90 bottom
C205  1uF  [0402]  145.64 108.46 180 bottom
C206  1uF  [0402]  146.91 108.46 180 bottom
C207  22uF  [0805]  142.21 106.17 270 bottom
C208  22uF  [0805]  142.21 108.46 270 bottom
C209  DNI  [1411]  90.24 74.94 270 bottom
C210  DNI  [1411]  86.33 75.06 270 bottom
C211  22uF  [0805]  142.21 110.74 270 bottom
C212  22uF  [0805]  80.87 100.2 90 bottom
C213  1uF  [0201]  113.93 108.6 90 bottom
C214  1uF  [0201]  113.93 94.6 270 bottom
C215  1uF  [0201]  115.66 94.6 270 bottom
C216  1uF  [0201]  112.19 94.6 270 bottom
C217  1uF  [0201]  112.19 108.6 90 bottom
C218  1uF  [0201]  110.46 94.6 270 bottom
C222  1uF  [0201]  121.29 91.85 150 bottom
C223  1uF  [0201]  121.29 92.85 150 bottom
C224  1uF  [0201]  124.75 92.85 150 bottom
C225  1uF  [0201]  124.75 91.85 150 bottom
C226  1uF  [0201]  103.1 112.35 150 bottom
C227  1uF  [0201]  103.1 111.35 150 bottom
C228  1uF  [0201]  111.76 90.85 210 bottom
C229  1uF  [0201]  108.3 90.85 210 bottom
C230  1uF  [0201]  110.03 90.85 210 bottom
C231  1uF  [0201]  110.89 112.35 30 bottom
C232  1uF  [0201]  112.12 112.6 90 bottom
C233  1uF  [0201]  114.36 112.35 30 bottom
C234  1uF  [0201]  113.49 90.85 210 bottom
C235  1uF  [0201]  109.16 112.35 30 bottom
C245  10uF  [0402]  81.98 88.02 270 bottom
C246  10uF  [0402]  81.98 87.02 270 bottom
C247  10uF  [0603]  151.1 115.32 270 bottom
C248  10uF  [0603]  149.07 115.32 270 bottom
C249  10uF  [0603]  147.04 115.32 270 bottom
C250  10uF  [0603]  145.01 115.32 270 bottom
C252  47uf  [1206]  132.31 75.44 270 bottom
C253  100uF  [0805]  80.87 95.12 90 bottom
C254  1uF  [0201]  125.62 103.85 30 bottom
C255  1uF  [0201]  125.62 102.85 30 bottom
C256  1uF  [0201]  123.89 103.35 150 bottom
C257  1uF  [0201]  123.89 104.35 150 bottom
C258  0.1uF  [0201]  124.75 101.35 30 bottom
C259  0.1uF  [0201]  123.89 99.85 210 bottom
C260  0.1uF  [0201]  123.89 106.35 150 bottom
C261  100uF  [0805]  81.73 77.64 90 bottom
C262  1uF  [0201]  123.02 98.85 150 bottom
C263  1uF  [0201]  124.75 98.85 150 bottom
C268  1uF  [0201]  98.77 97.85 150 bottom
C269  1uF  [0201]  99.64 96.35 330 bottom
C270  1uF  [0201]  98.77 95.35 210 bottom
C271  1uF  [0201]  98.77 101.35 210 bottom
C272  1uF  [0201]  99.2 103.1 90 bottom
C273  22uF  [0603]  81.98 85.77 180 bottom
C274  22uF  [0603]  81.98 84.27 180 bottom
C275  4.7uF  [0201]  116.09 93.35 210 bottom
C276  4.7uF  [0201]  118.69 111.35 330 bottom
C277  4.7uF  [0201]  116.09 108.85 150 bottom
C278  4.7uF  [0201]  116.96 109.35 330 bottom
C279  4.7uF  [0201]  113.49 92.35 330 bottom
C280  4.7uF  [0201]  115.23 110.35 330 bottom
C281  4.7uF  [0201]  111.76 111.35 330 bottom
C282  4.7uF  [0201]  105.7 92.35 210 bottom
C283  4.7uF  [0201]  105.7 110.35 210 bottom
C284  4.7uF  [0201]  108.73 108.6 90 bottom
C285  1uF  [0201]  105.27 94.6 270 bottom
C286  1uF  [0201]  105.27 108.6 90 bottom
C287  1uF  [0201]  107 108.6 90 bottom
C288  1uF  [0201]  116.96 94.35 330 bottom
C289  1uF  [0201]  106.56 94.85 210 bottom
C290  1uF  [0201]  113.49 110.85 30 bottom
C291  1uF  [0201]  114.79 91.1 270 bottom
C292  1uF  [0201]  116.96 110.35 330 bottom
C293  10uF  [0603]  105.19 125.22 270 bottom
C294  10uF  [0603]  102.08 125.22 270 bottom
C312  0.1uF  [0402]  117.39 91.6 0 bottom
C313  0.1uF  [0402]  116.09 112.35 300 bottom
C314  0.1uF  [0402]  116.09 90.85 240 bottom
C315  0.1uF  [0402]  107.43 112.35 300 bottom
C316  0.1uF  [0402]  104.87 112.27 60 bottom
C317  0.1uF  [0402]  104.85 90.85 120 bottom
C318  0.1uF  [0402]  117.82 112.35 300 bottom
C328  DNI  [7343P]  97.76 46.51 180 bottom
C337  10uF  [0603]  100.56 75.06 90 bottom
C338  10uF  [0603]  98.78 75.06 90 bottom
C339  47uF  [0805]  80.9 97.41 90 bottom
C344  1uF  [0201]  119.56 92.35 210 bottom
C345  1uF  [0201]  119.56 91.35 210 bottom
C346  1uF  [0201]  102.23 110.85 150 bottom
C347  1uF  [0201]  102.23 108.85 150 bottom
C348  10uF  [0603]  137.89 75.69 90 bottom
C349  10uF  [0603]  64.11 96.52 0 bottom
C350  47uF  [0805]  75.16 88.77 90 bottom
C351  47uF  [0805]  75.16 86.49 90 bottom
C352  47uF  [0805]  75.16 91.06 90 bottom
C371  1uF  [0201]  126.92 91.1 270 bottom
C372  0.1uF  [0402]  75.56 60.45 180 bottom
C373  1uF  [0402]  76.83 60.45 180 bottom
C374  0.1uF  [0402]  78.59 59.94 90 bottom
C375  0.1UF  [0402]  90.4 62.1 270 bottom
C377  1uF  [0402]  115.01 55.09 0 bottom
C387  1uF  [0402]  116.56 51.05 180 bottom
C395  47uF  [0805]  87.53 64.67 0 bottom
C399  10uF  [0603]  113.56 49.86 0 bottom
C400  0.1UF  [0402]  113.87 51.69 90 bottom
C406  0.1uF  [0402]  91.82 151 0 bottom
C407  0.1uF  [0402]  103.25 151 0 bottom
C452  0.1uF  [0402]  114.55 151 0 bottom
C453  0.1uF  [0402]  125.98 151 0 bottom
C486  10uF  [0603]  72.81 173.22 270 top
C487  10uF  [0603]  75.09 173.22 270 top
C489  100pF  [0402]  62.87 177.42 90 top
C491  47uf  [1206]  67.56 170.28 180 top
C492  47uf  [1206]  67.56 167.36 180 top
C497  0.01uF  [0402]  62.87 180.21 90 top
C498  0.1uF  [0402]  80.74 150.88 0 bottom
C519  0.01uF  [0402]  119.28 148.92 270 bottom
C520  10uF  [0603]  185.67 82.04 0 bottom
C521  0.1uF  [0402]  184.91 79.12 270 bottom
C522  0.1uF  [0402]  184.91 80.39 270 bottom
C523  10uF  [0603]  185.42 107.06 0 bottom
C524  10uF  [0603]  189.74 82.17 180 bottom
C525  0.1uF  [0402]  190.5 79.25 90 bottom
C526  0.1uF  [0402]  190.5 80.52 90 bottom
C527  10uF  [0603]  190.17 106.5 180 bottom
C528  0.1uF  [0402]  184.91 104.39 270 bottom
C529  0.1uF  [0402]  184.91 105.36 270 bottom
C530  0.1uF  [0402]  190.47 105.23 90 bottom
C531  0.1uF  [0402]  190.5 104.34 90 bottom
C532  10uF  [0603]  190.3 95.22 180 bottom
C533  0.1uF  [0402]  190.5 93.6 90 bottom
C534  0.1uF  [0402]  183.87 93.85 270 bottom
C535  10uF  [0603]  189.87 120.78 180 bottom
C536  0.1uF  [0402]  185.34 119.02 90 bottom
C537  0.1uF  [0402]  190.5 119 90 bottom
C544  0.1uF  [0402]  64.39 71.37 180 top
C545  22uf  [1210]  66.55 73.03 90 top
C546  0.1uF  [0402]  54.46 86.2 0 bottom
C547  1uF  [0402]  55.47 86.2 0 bottom
C548  0.1uF  [0402]  64.87 84.45 90 bottom
C549  0.1uF  [0402]  65.66 85.47 90 bottom
C550  1uF  [0402]  65.66 86.49 90 bottom
C551  0.1uF  [0402]  67.21 73.86 90 bottom
C552  22uf  [1210]  66.75 66.72 180 bottom
C553  0.1uF  [0402]  56.36 83.88 180 bottom
C554  0.1uF  [0402]  64.39 69.22 0 top
C555  22uf  [1210]  66.55 67.56 270 top
C556  0.1uF  [0402]  46.14 68.2 180 bottom
C557  22uf  [1210]  43.47 67.06 270 bottom
C558  1000pF  [1206]  13.03 53.77 270 bottom
C559  0.1uF  [0402]  36.3 89.46 180 bottom
C560  22uF  [0603]  34.39 89.59 90 bottom
C561  0.1uF  [0402]  51.56 95 180 top
C562  10uF  [0603]  54.36 95 270 top
C563  22uF  [0603]  52.83 95 270 top
C564  22uF  [0603]  55.88 95 270 top
C565  0.1uF  [0402]  42.39 92.96 180 bottom
C566  10uF  [0603]  37.01 92.91 90 bottom
C567  22uF  [0603]  39.04 92.91 90 bottom
C568  22uF  [0603]  40.94 92.91 90 bottom
C569  0.1uF  [0402]  51.56 98.55 180 top
C570  10uF  [0603]  54.36 98.55 270 top
C571  22uF  [0603]  52.83 98.55 270 top
C572  22uF  [0603]  55.88 98.55 270 top
C573  0.1uF  [0402]  65.56 93.16 0 bottom
C574  1uF  [0402]  66.83 93.16 0 bottom
C575  0.1uF  [0402]  64.9 90.68 90 bottom
C576  0.1uF  [0402]  55.12 92.2 90 bottom
C577  1uF  [0402]  55.12 93.22 90 bottom
C578  0.1uF  [0402]  54.48 91.19 90 bottom
C579  1000pF  [1206]  10.51 109.35 90 bottom
C580  0.1uF  [0402]  212.6 22.35 270 top
C581  0.22uF  [0402]  212.6 30.74 270 top
C582  0.1uF  [0402]  198.37 25.27 0 top
C583  0.1uF  [0402]  199.64 25.27 0 top
C584  100uF  [1206]  196.22 25.91 270 top
C585  0.1uF  [0402]  212.6 24.89 270 top
C586  0.22uF  [0402]  212.6 31.56 270 top
C587  0.22uF  [0402]  212.6 35.74 270 top
C588  0.22uF  [0402]  212.6 36.56 270 top
C589  0.22uF  [0402]  212.6 39.74 270 top
C590  0.22uF  [0402]  212.6 40.56 270 top
C591  0.22uF  [0402]  212.6 43.74 270 top
C592  0.22uF  [0402]  212.6 44.56 270 top
C593  0.22uF  [0402]  212.6 49.74 270 top
C594  0.22uF  [0402]  212.6 50.56 270 top
C595  0.22uF  [0402]  212.6 53.74 270 top
C596  0.22uF  [0402]  212.6 54.56 270 top
C597  0.22uF  [0402]  212.6 57.74 270 top
C598  0.22uF  [0402]  212.6 58.56 270 top
C599  0.22uF  [0402]  212.6 61.74 270 top
C600  0.22uF  [0402]  212.6 62.56 270 top
C601  0.22uF  [0402]  212.6 66.74 270 top
C602  0.22uF  [0402]  212.6 67.56 270 top
C603  0.22uF  [0402]  212.6 70.74 270 top
C604  0.22uF  [0402]  212.6 71.56 270 top
C605  0.22uF  [0402]  212.6 74.74 270 top
C606  0.22uF  [0402]  212.6 75.56 270 top
C607  0.22uF  [0402]  212.6 78.74 270 top
C608  22uF  [1206]  202.41 15.49 180 bottom
C609  22uF  [1206]  192.76 13.33 0 top
C610  0.1uF  [0402]  212.6 16.26 270 top
C611  0.1uF  [0402]  212.6 17.53 270 top
C612  0.1uF  [0402]  212.6 14.99 270 top
C613  0.1uF  [0402]  204.57 18.16 180 bottom
C614  0.1uF  [0402]  203.55 18.16 180 bottom
C615  0.22uF  [0402]  212.6 79.56 270 top
C616  0.22uF  [0402]  212.6 82.74 270 top
C617  0.22uF  [0402]  212.6 83.56 270 top
C618  0.22uF  [0402]  212.6 86.74 270 top
C619  0.22uF  [0402]  212.6 87.56 270 top
C620  0.22uF  [0402]  212.6 90.74 270 top
C621  0.22uF  [0402]  212.6 91.56 270 top
C622  0.22uF  [0402]  212.6 94.74 270 top
C623  0.22uF  [0402]  212.6 95.56 270 top
C624  1000pF  [1206]  9.42 25.48 0 top
C625  0.1uF  [0402]  20.62 15.65 270 bottom
C626  1uF  [0402]  35.94 22.02 0 bottom
C627  0.1uF  [0402]  33.3 20.9 0 bottom
C628  0.1uF  [0402]  32 15.75 90 top
C629  0.1uF  [0402]  32 14.48 90 top
C630  0.1uF  [0402]  32 13.21 90 top
C631  0.1uF  [0402]  32 11.94 90 top
C632  0.01uF  [0402]  20.08 8.19 90 bottom
C633  0.01uF  [0402]  18.41 17.53 90 bottom
C634  0.01uF  [0402]  18.97 14.35 90 bottom
C635  0.01uF  [0402]  18.97 13.11 90 bottom
C636  0.01uF  [0402]  19.25 9.93 90 bottom
C637  0.1uF  [0402]  28.49 20.38 0 bottom
C638  0.1uF  [0402]  25.58 17.68 180 bottom
C639  0.1uF  [0402]  30.16 15.62 270 bottom
C640  0.1uF  [0402]  23.25 10.54 90 bottom
C641  0.1uF  [0402]  27.18 17.65 180 bottom
C642  0.1uF  [0402]  27.29 20.37 0 bottom
C643  0.1uF  [0402]  34.52 22.02 0 bottom
C644  0.1uF  [0402]  27.44 16.14 90 bottom
C645  0.1uF  [0402]  22.49 19.49 180 bottom
C646  0.1uF  [0402]  30.12 18.84 270 bottom
C647  0.1uF  [0402]  27.33 13.94 90 bottom
C648  0.1uF  [0402]  22.38 14.35 270 bottom
C649  0.1uF  [0402]  21.95 12.22 180 bottom
C650  0.1uF  [0402]  158.85 147.19 180 bottom
C651  1uF  [0402]  159.87 147.19 180 bottom
C652  0.1uF  [0402]  157.1 148.21 270 bottom
C653  0.1uF  [0402]  151 134.62 90 bottom
C654  1uF  [0402]  151 133.35 90 bottom
C655  0.1uF  [0402]  151 132.08 90 bottom
C656  0.1uF  [0402]  162.63 136.07 180 bottom
C657  1uF  [0402]  163.17 137.92 270 bottom
C658  0.1uF  [0402]  166.37 207.14 90 bottom
C659  1uF  [0402]  166.37 208.41 90 bottom
C660  0.1uF  [0402]  169.06 208.41 270 bottom
C661  0.1uF  [0402]  159.77 207.26 90 bottom
C662  1uF  [0402]  159.77 208.53 90 bottom
C663  0.1uF  [0402]  162.43 208.53 270 bottom
C664  0.1uF  [0402]  33.75 152.27 90 bottom
C665  12pF  [0402]  15.9 179.65 270 top
C666  12pF  [0402]  17.81 179.65 90 top
C667  1000pF  [1206]  12.47 166.17 0 bottom
C668  0.1uF  [0402]  16.25 172.08 90 top
C669  0.1uF  [0402]  27.24 182.27 90 top
C670  0.1uF  [0402]  28.42 174.75 90 bottom
C671  0.1uF  [0402]  35.56 175.51 180 bottom
C672  0.1uF  [0402]  19.18 177.05 0 bottom
C673  0.1uF  [0402]  26.82 172.92 0 bottom
C674  0.1uF  [0402]  18.81 178.66 90 bottom
C675  0.1uF  [0402]  20.85 181.32 90 bottom
C676  0.1uF  [0402]  19.13 175.04 0 bottom
C677  0.1uF  [0402]  21.74 172.92 0 bottom
C678  0.1uF  [0402]  30.1 159.64 180 bottom
C679  0.1uF  [0402]  39.12 135.13 180 bottom
C680  1uF  [0402]  27.56 135.13 180 bottom
C681  0.1uF  [0402]  28.83 135.13 180 bottom
C682  0.1uF  [0402]  30.1 159.64 0 top
C683  1uF  [0402]  27.69 159.64 0 top
C684  0.1uF  [0402]  28.96 159.64 0 top
C685  0.1uF  [0402]  24.39 167.77 0 top
C686  DNI  [0402]  13.33 142.9 0 top
C687  10uF  [0603]  43.69 181.86 90 bottom
C688  0.1uF  [0402]  35.1 171.22 270 bottom
C689  0.1uF  [0402]  41.63 168.76 270 bottom
C690  0.1uF  [0402]  38.96 172.59 270 bottom
C691  0.1uF  [0402]  38.23 164.21 180 bottom
C692  0.1uF  [0402]  39.12 164.21 180 bottom
C693  0.1uF  [0402]  38.71 181.45 0 bottom
C694  0.1uF  [0402]  35.15 181.45 0 bottom
C695  0.1uF  [0402]  34.26 181.45 0 bottom
C696  0.1uF  [0402]  38.73 171.07 180 bottom
C697  0.1uF  [0402]  40.01 164.21 180 bottom
C698  10uF  [0603]  40.39 181.86 90 bottom
C699  0.1uF  [0402]  40.89 164.21 180 bottom
C700  0.1uF  [0402]  39.12 174.37 90 bottom
C701  0.1uF  [0402]  36.04 181.45 0 bottom
C702  0.1uF  [0402]  32.23 171.96 180 bottom
C703  0.1uF  [0402]  39.85 169.54 90 bottom
C704  0.1uF  [0402]  33.25 173.1 0 bottom
C705  0.1uF  [0402]  45.09 181.48 0 bottom
C706  0.1uF  [0402]  45.97 181.48 0 bottom
C707  0.1uF  [0402]  38.07 168.27 180 bottom
C708  0.1uF  [0402]  36.93 181.45 0 bottom
C709  10uF  [0603]  42.04 181.86 90 bottom
C710  0.1uF  [0402]  38.35 179.07 90 bottom
C711  0.1uF  [0402]  37.08 176.43 0 bottom
C712  0.1uF  [0402]  37.31 173.15 180 bottom
C713  0.1uF  [0402]  37.82 181.45 0 bottom
C714  0.1uF  [0402]  38.73 176.02 180 bottom
C715  0.1uF  [0402]  37.31 164.21 180 bottom
C716  0.1uF  [0402]  30.83 171.83 180 bottom
C717  0.1uF  [0402]  34.59 173.02 0 bottom
C718  0.1uF  [0402]  36.01 172.62 270 bottom
C719  10uF  [0603]  33.4 161.26 180 bottom
C720  0.1uF  [0402]  35.13 167.13 270 bottom
C721  0.1uF  [0402]  33.51 162.4 90 bottom
C722  0.1uF  [0402]  33.55 163.3 90 bottom
C723  0.1uF  [0402]  35.91 168.02 270 bottom
C724  0.1uF  [0402]  42.36 167.76 270 bottom
C725  0.1uF  [0402]  35.81 163.7 270 bottom
C726  0.1uF  [0402]  33.55 164.18 90 bottom
C727  10uF  [0603]  47.12 170.03 0 bottom
C728  0.1uF  [0402]  47.12 171.3 270 bottom
C729  0.1uF  [0402]  47.12 172.34 270 bottom
C730  0.1uF  [0402]  40.77 172.59 90 bottom
C731  0.1uF  [0402]  47.12 173.23 270 bottom
C732  10uF  [0603]  50.55 175.26 0 bottom
C733  0.1uF  [0402]  49.91 172.72 270 bottom
C734  0.1uF  [0402]  49.91 173.99 270 bottom
C735  10uF  [0603]  39.37 161.97 0 bottom
C736  0.1uF  [0402]  34.01 175.51 0 bottom
C737  0.1uF  [0402]  32.36 174.12 180 bottom
C738  0.1uF  [0402]  32.36 176.53 0 bottom
C740  10uF  [0603]  165.86 104.01 90 bottom
C741  0.1uF  [0402]  162.94 103.25 0 bottom
C742  0.1uF  [0402]  164.21 103.25 0 bottom
C743  0.1uF  [0402]  173.35 103.25 0 bottom
C744  0.1uF  [0402]  171.86 93.57 90 bottom
C745  0.1uF  [0402]  176.66 103.25 0 bottom
C746  0.1uF  [0402]  168.37 92.33 0 bottom
C747  0.1uF  [0402]  167.39 93.98 0 bottom
C748  0.1uF  [0402]  173.99 96.34 180 bottom
C749  10uF  [0603]  175.01 104.01 90 bottom
C750  0.1uF  [0402]  167.39 91.57 180 bottom
C751  0.1uF  [0402]  173.81 90.7 180 bottom
C752  0.1uF  [0402]  166.19 88.72 270 bottom
C753  0.1uF  [0402]  170.26 94.41 270 bottom
C754  10uF  [0603]  166.75 83.95 270 bottom
C755  0.1uF  [0402]  177.93 103.25 180 bottom
C756  0.1uF  [0402]  167.51 103.25 0 bottom
C757  0.1uF  [0402]  168.4 84.33 180 bottom
C758  0.1uF  [0402]  164.64 86.31 90 bottom
C759  0.1uF  [0402]  168.66 89.69 270 bottom
C760  0.1uF  [0402]  167.94 88.67 90 bottom
C761  0.1uF  [0402]  169.67 84.33 180 bottom
C762  10uF  [0603]  176.53 83.95 270 bottom
C763  0.1uF  [0402]  172.21 84.33 180 bottom
C764  0.1uF  [0402]  170.94 84.33 180 bottom
C765  0.1uF  [0402]  173.48 84.33 180 bottom
C766  0.1uF  [0402]  174.75 84.33 180 bottom
C767  10uF  [0603]  169.16 104.01 90 bottom
C768  0.1uF  [0402]  160.53 99.95 90 bottom
C769  0.1uF  [0402]  160.53 97.41 90 bottom
C770  0.1uF  [0402]  169.47 97.59 270 bottom
C771  0.1uF  [0402]  167.51 96.39 0 bottom
C772  0.1uF  [0402]  160.53 98.68 90 bottom
C773  0.1uF  [0402]  172.09 103.25 0 bottom
C774  0.1uF  [0402]  170.81 103.25 0 bottom
C775  0.1uF  [0402]  160.53 96.14 90 bottom
C776  10uF  [0603]  180.85 89.53 0 bottom
C777  0.1uF  [0402]  180.34 100.84 270 bottom
C778  0.1uF  [0402]  180.19 96.82 270 bottom
C779  0.1uF  [0402]  180.34 102.23 270 bottom
C780  0.1uF  [0402]  180.34 103.5 270 bottom
C781  0.1uF  [0402]  171.83 91.31 90 bottom
C782  10uF  [0603]  180.21 98.17 0 bottom
C783  0.1uF  [0402]  175.18 92 270 bottom
C784  0.1uF  [0402]  180.14 95.5 270 bottom
C785  0.1uF  [0402]  180.34 99.57 270 bottom
C786  0.1uF  [0402]  173.86 93.98 0 bottom
C787  0.1uF  [0402]  172.26 89.97 180 bottom
C788  0.1uF  [0402]  180.34 105.03 270 bottom
C789  0.1uF  [0402]  172.97 97.21 0 bottom
C790  0.1uF  [0402]  171.52 97.18 180 bottom
C791  100pF  [0402]  167.13 113.79 0 top
C792  100pF  [0402]  167.13 111.76 0 top
C793  100pF  [0402]  169.93 115.44 270 top
C794  0.1uF  [0402]  175.26 113.28 270 top
C795  100pF  [0402]  167.13 109.73 0 top
C796  1uF  [0402]  175.26 110.74 90 top
C797  10uF  [1210]  183.08 132.99 180 bottom
C798  0.1uF  [0402]  183.13 130.3 270 bottom
C799  10uF  [1210]  17.88 113.03 270 bottom
C800  0.1uF  [0402]  20.42 114.05 0 bottom
C801  220pF  [0402]  41.27 46.61 90 bottom
C802  0.01uF  [0402]  41.27 47.88 270 bottom
C803  0.1uF  [0402]  43.99 45.57 90 bottom
C804  10uF  [0603]  44.15 47.24 180 bottom
C805  220pF  [0402]  18.41 48.41 0 bottom
C806  0.01uF  [0402]  19.68 48.41 180 bottom
C807  0.1uF  [0402]  19.35 45.93 0 bottom
C808  10uF  [0603]  21.01 46.3 90 bottom
C809  0.1uF  [0402]  62.74 22.16 0 top
C810  0.1uF  [0402]  63.75 22.16 0 top
C811  0.1uF  [0402]  62.74 7.18 180 top
C812  0.1uF  [0402]  80.26 34.16 90 bottom
C813  0.1uF  [0402]  63.75 7.18 180 top
C814  0.1uF  [0402]  80.26 35.18 90 bottom
C815  0.1uF  [0402]  86.47 41.02 0 bottom
C816  0.1uF  [0402]  87.49 41.02 0 bottom
C817  0.1uF  [0402]  92.3 34.54 90 bottom
C818  0.1uF  [0402]  92.3 33.53 90 bottom
C819  1uF  [0402]  97.16 37.85 90 bottom
C820  0.1uF  [0402]  97.16 38.99 270 bottom
C821  1uF  [0402]  88.01 30.73 180 bottom
C822  1uF  [0402]  89.28 30.73 180 bottom
C823  1uF  [0402]  89.41 39.5 0 bottom
C824  18pF  [0402]  166.6 139.89 180 top
C825  1uF  [0402]  159.04 141.33 180 top
C826  1uF  [0402]  162.5 141.08 180 top
C827  1uF  [0402]  170.28 137.03 90 top
C828  1uF  [0402]  159.9 133.33 270 top
C829  18pF  [0402]  165.2 139.89 180 top
C830  DNI  [0402]  151.99 29.21 180 bottom
C831  0.1uF  [0402]  159.74 30.73 270 bottom
C832  0.1uF  [0402]  156.46 35 0 bottom
C833  0.1uF  [0402]  154.43 27.51 180 bottom
C834  0.1uF  [0402]  156.59 27.51 180 bottom
C835  0.1uF  [0402]  153.8 35.89 0 bottom
C836  0.1uF  [0402]  159.74 31.75 270 bottom
C837  DNI  [0402]  151.99 31.24 0 bottom
C838  0.1uF  [0402]  161.9 34.29 270 bottom
C839  0.1uF  [0402]  161.9 33.02 270 bottom
C840  0.1uF  [0402]  161.9 29.21 270 bottom
C841  0.1uF  [0402]  158.12 101.85 270 top
C842  0.1uF  [0402]  161.9 27.94 270 bottom
C843  DNI  [0402]  47.47 107.31 180 bottom
C844  0.1uF  [0402]  54.99 108.84 270 bottom
C845  0.1uF  [0402]  51.94 112.9 0 bottom
C846  0.1uF  [0402]  49.4 112.9 0 bottom
C847  DNI  [0402]  47.47 109.22 0 bottom
C848  0.1uF  [0402]  52.2 105.41 180 bottom
C849  0.1uF  [0402]  49.66 104.78 180 bottom
C850  0.1uF  [0402]  54.99 110.11 270 bottom
C851  0.1uF  [0402]  53.47 160.02 270 top
C852  0.1uF  [0402]  57.28 111.33 270 bottom
C853  0.1uF  [0402]  57.28 110.06 270 bottom
C854  10uF  [C0805]  178.79 44.45 90 bottom
C855  10uF  [C0805]  188.82 47.24 270 bottom
C856  10uF  [C0805]  184 63.63 0 bottom
C857  0.1uF  [0402]  186.41 51.94 180 bottom
C858  0.1uF  [0402]  182.98 51.94 180 bottom
C859  0.1uF  [0201]  187.32 64.01 270 top
C860  0.1uF  [0201]  186.31 64.01 270 top
C861  0.1uF  [0402]  193.11 56.01 90 top
C862  0.1uF  [0201]  180.59 64.01 270 top
C863  0.1uF  [0201]  179.58 64.01 270 top
C865  0.1uF  [0201]  183.13 64.01 270 top
C866  0.1uF  [0402]  193.14 57.02 90 top
C868  0.1uF  [0201]  182.12 64.01 270 top
C869  0.1uF  [0201]  174.72 52.7 180 top
C870  0.1uF  [0201]  174.72 51.56 180 top
C871  0.1uF  [0201]  180.09 48.77 270 top
C872  0.1uF  [0201]  179.07 48.77 270 top
C873  0.1uF  [0201]  193.17 51.82 0 top
C874  0.1uF  [0201]  193.17 52.83 0 top
C875  0.1uF  [0201]  191.13 54.99 0 top
C876  0.1uF  [0201]  191.13 53.98 0 top
C882  0.1uF  [0402]  172.21 44.22 180 top
C883  10uF  [C0805]  175.49 43.69 180 top
C884  10uF  [C0805]  178.79 44.45 270 top
C885  0.1uF  [0402]  178.53 42.29 180 top
C886  0.1uF  [0402]  199.01 67.69 0 bottom
C887  10uF  [C0805]  195.45 67.69 0 bottom
C888  0.1uF  [0402]  186.92 60.32 0 bottom
C889  0.1uF  [0402]  178.92 57.78 90 bottom
C890  10uF  [C0805]  174.34 59.44 0 bottom
C891  0.1uF  [0402]  169.39 57.28 0 bottom
C892  0.1uF  [0402]  175.72 71.35 90 bottom
C893  10uF  [C0805]  176.02 67.28 90 bottom
C894  0.1uF  [0402]  179.8 60.83 0 bottom
C895  0.1uF  [0402]  174.34 58.8 90 top
C896  DNI  [0402]  174.34 60.07 270 top
C897  0.1uF  [0402]  178.92 55.24 90 bottom
C898  10uF  [C0805]  174.37 55.5 180 bottom
C899  0.1uF  [0402]  169.39 55.12 0 bottom
C900  0.1uF  [0402]  178.43 71.27 90 bottom
C901  10uF  [C0805]  179.93 67.28 90 bottom
C902  0.1uF  [0402]  182.73 60.32 0 bottom
C903  0.1uF  [0402]  178.92 53.34 90 bottom
C904  10uF  [C0805]  176.66 51.82 180 bottom
C905  0.1uF  [0402]  171.83 51.69 180 bottom
C906  0.1uF  [0402]  191.97 71.48 270 bottom
C907  10uF  [C0805]  191.97 67.92 270 bottom
C908  0.1uF  [0402]  185.77 60.32 0 bottom
C909  0.1uF  [0402]  176.38 46.99 270 bottom
C910  10uF  [C0805]  176.38 48.77 90 bottom
C911  0.1uF  [0402]  188.19 53.21 270 bottom
C912  10uF  [C0805]  195.45 55.63 0 bottom
C913  0.1uF  [0402]  199.01 55.63 0 bottom
C914  0.1uF  [0402]  181.71 51.94 180 bottom
C915  0.1uF  [0402]  187.91 71.48 90 bottom
C916  10uF  [C0805]  187.91 67.92 90 bottom
C917  0.1uF  [0402]  183.87 60.32 0 bottom
C918  0.1uF  [0402]  199.01 51.56 0 bottom
C919  0.1uF  [0402]  188.31 57.4 270 bottom
C920  10uF  [C0805]  195.45 59.69 0 bottom
C921  0.1uF  [0402]  199.01 59.69 0 bottom
C922  10uF  [C0805]  195.45 51.56 0 bottom
C923  0.1uF  [0402]  188.19 52.07 270 bottom
C924  0.1uF  [0402]  175.11 65.28 90 bottom
C925  10uF  [C0805]  177.26 64.01 0 bottom
C926  0.1uF  [0402]  178.92 58.93 90 bottom
C927  0.1uF  [0402]  188.31 59.31 270 bottom
C928  10uF  [C0805]  195.45 63.75 180 bottom
C929  0.1uF  [0402]  199.01 63.75 180 bottom
C930  0.1uF  [0402]  191.62 43.05 90 bottom
C931  10uF  [C0805]  188.82 44.96 270 bottom
C932  0.1uF  [0402]  184.25 51.94 180 bottom
C933  0.1uF  [0402]  180.85 70.1 0 bottom
C934  1uF  [0402]  181.86 70.1 0 bottom
C935  0.1uF  [0402]  183.54 70.61 270 bottom
C936  0.1uF  [0402]  166.5 52.32 90 bottom
C937  1uF  [0402]  166.52 53.52 90 bottom
C938  0.1uF  [0402]  166.12 55.24 0 bottom
C939  0.1uF  [0402]  166.52 48.92 90 bottom
C940  1uF  [0402]  166.52 47.9 90 bottom
C941  0.1uF  [0402]  165.99 50.67 0 bottom
C942  0.1uF  [0402]  178.56 125.73 180 top
C943  0.1uF  [0402]  179.2 128.52 0 top
C944  0.1uF  [0402]  61.47 47.37 270 bottom
C945  0.1uF  [0402]  170.31 125.73 180 top
C946  0.1uF  [0402]  170.94 128.27 0 top
C947  0.1uF  [0402]  146.71 33.09 90 bottom
C948  DNI  [0402]  8.86 190.12 90 bottom
C949  680pF  [0402]  8.61 207.64 270 bottom
C950  150uF  [7343P]  41.02 195.96 270 top
C951  150uF  [7343P]  40.99 195.96 270 bottom
C952  150uF  [7343P]  39.75 211.58 90 top
C953  150uF  [7343P]  39.75 211.58 90 bottom
C954  150uF  [7343P]  46.58 195.33 270 bottom
C955  DNI  [0402]  34.64 187.2 0 bottom
C956  0.01uF  [0402]  32.48 186.44 180 top
C957  1uF  [0402]  33.75 186.44 180 top
C958  0.01uF  [0402]  34.39 194.18 270 top
C965  0.1uF  [0402]  57.63 201.93 270 top
